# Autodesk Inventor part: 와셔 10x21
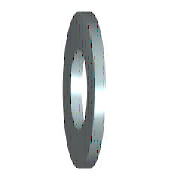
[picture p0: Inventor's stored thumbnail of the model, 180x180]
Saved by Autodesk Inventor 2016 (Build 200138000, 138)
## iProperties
Created: 2012-02
Part Number: 와셔 10x21
Material: 강철, 연강
Description: 평면 와셔
Document SubType Name: Modeling
Standard: KS B 1326
Designer: mduedu
Standards Organization: KS
Language: ko-KR
Size Designation: 10x21
Categories: <MemberInstance><Categories><Category DisplayName="조임쇠" InternalName="e4da775c-781d-43d5-af7c-5136215cf5a6" Mnemonic="FSTN"><Category DisplayName="와셔" InternalN
Density: 1 g/cm^3
Appearance: 파란색 - 벽 페인트 - 광택
IsCustomPart: 1
Author: mduedu
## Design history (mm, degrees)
sketch "스케치"
  geometry: C1 r 10.5 at (0, 0); C2 r 5.25 at (0, 0); 1 further point
  constraints: 2 centre point, 2 coincident
  dimensions: "d0" = 10.5 diameter of C2 (= SD1); "d1" = 21 diameter of C1 (= SD2)
extrude "본체" new body sketch "스케치" distance "d2" = 2 (= SD); taper "d3" = 0 deg
workaxis "Work Axis1"
workplane "Work Plane1"
body "Solid1"
other parameters: "SD1" = 10.5 [user parameter; used in 1 equation term], "SD2" = 21 [user parameter; used in 1 equation term], "SD" = 2 [user parameter; used in 1 equation term], "d4" = 0, "d5" = 0, "d6" = 0, "d7" = 0
